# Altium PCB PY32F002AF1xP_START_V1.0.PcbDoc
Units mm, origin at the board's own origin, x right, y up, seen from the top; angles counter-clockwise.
Board outline 53.97 x 29.21 mm, 2 copper layers (Top Layer, Bottom Layer); 29 components, 28 nets, 127 pads, 48 vias.
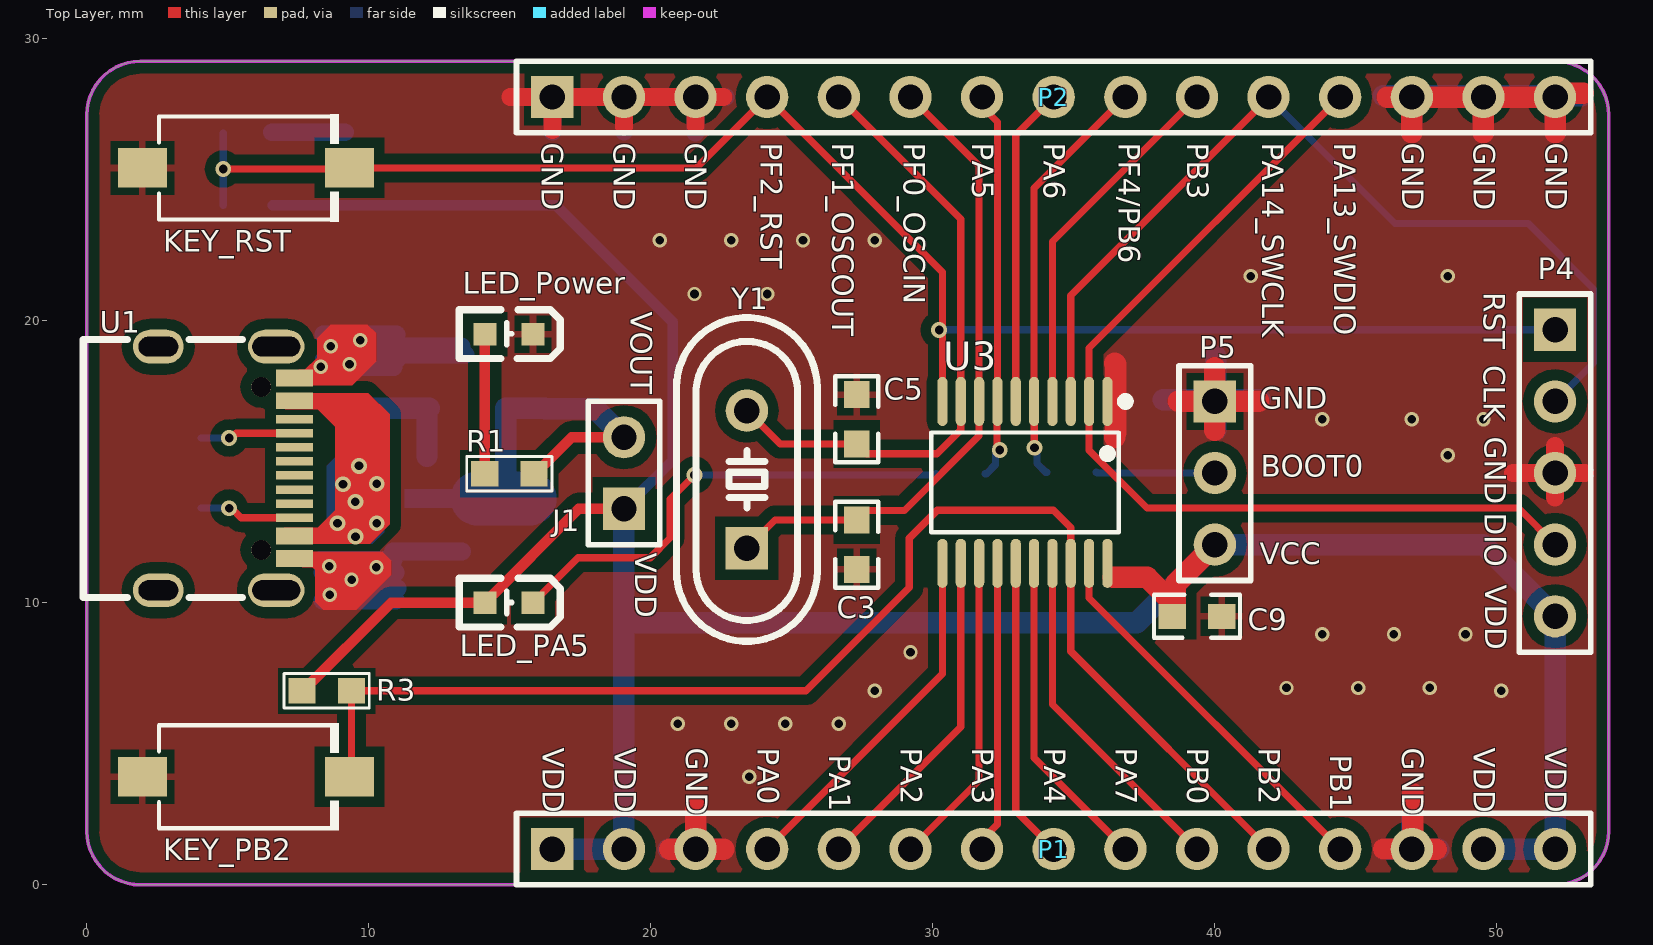
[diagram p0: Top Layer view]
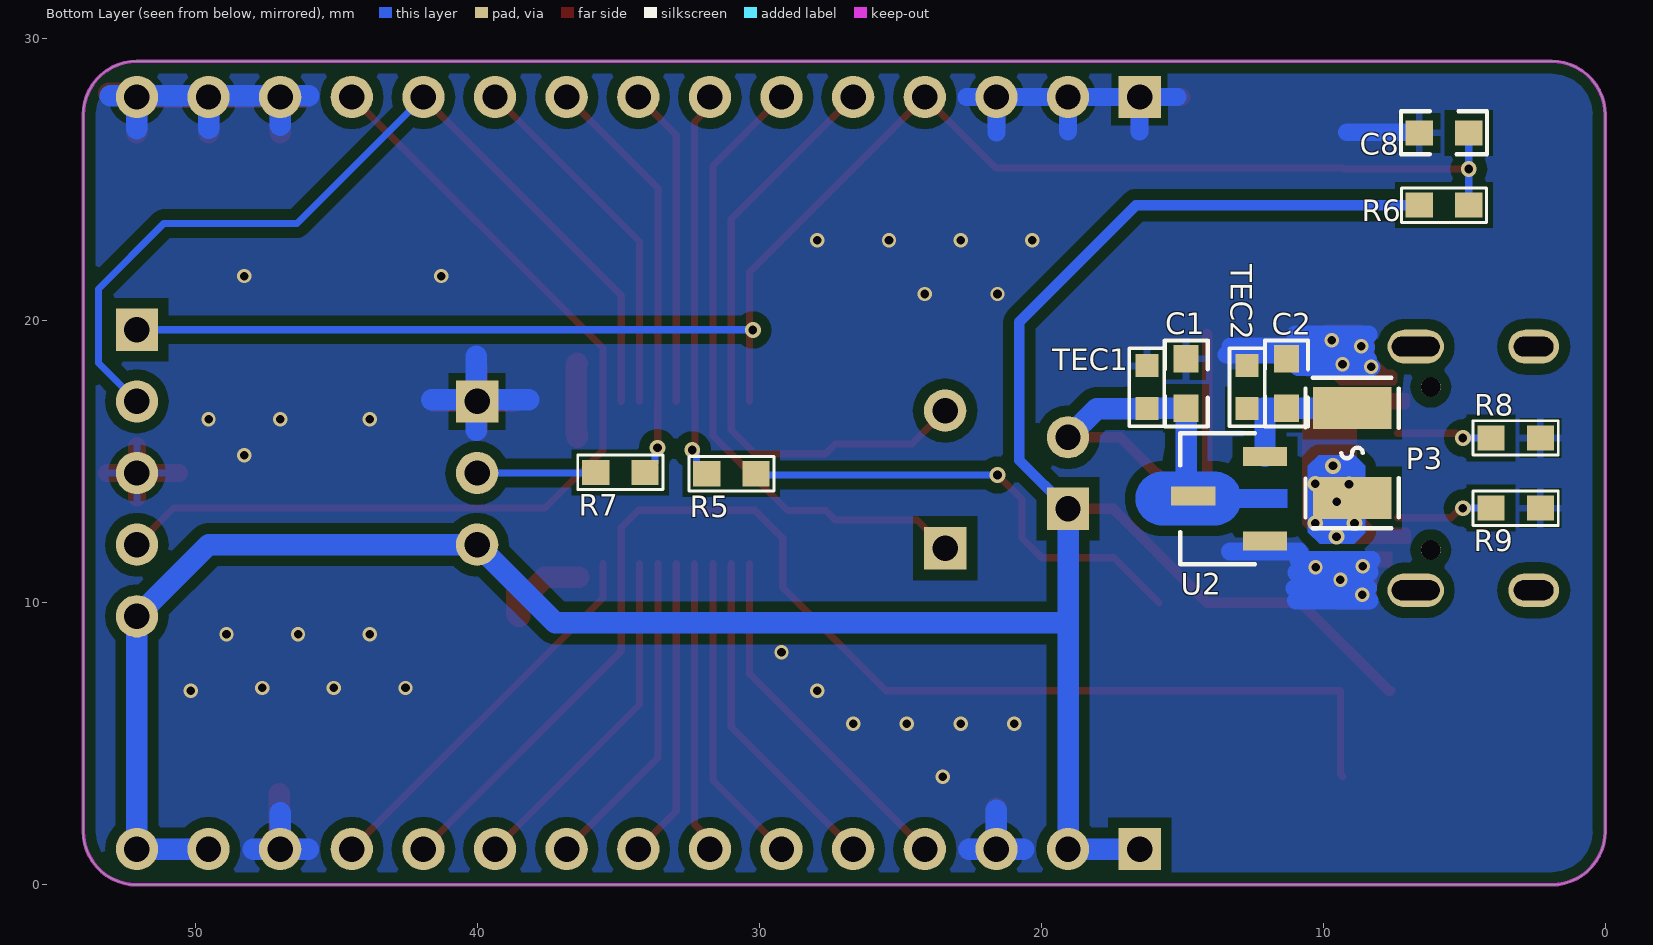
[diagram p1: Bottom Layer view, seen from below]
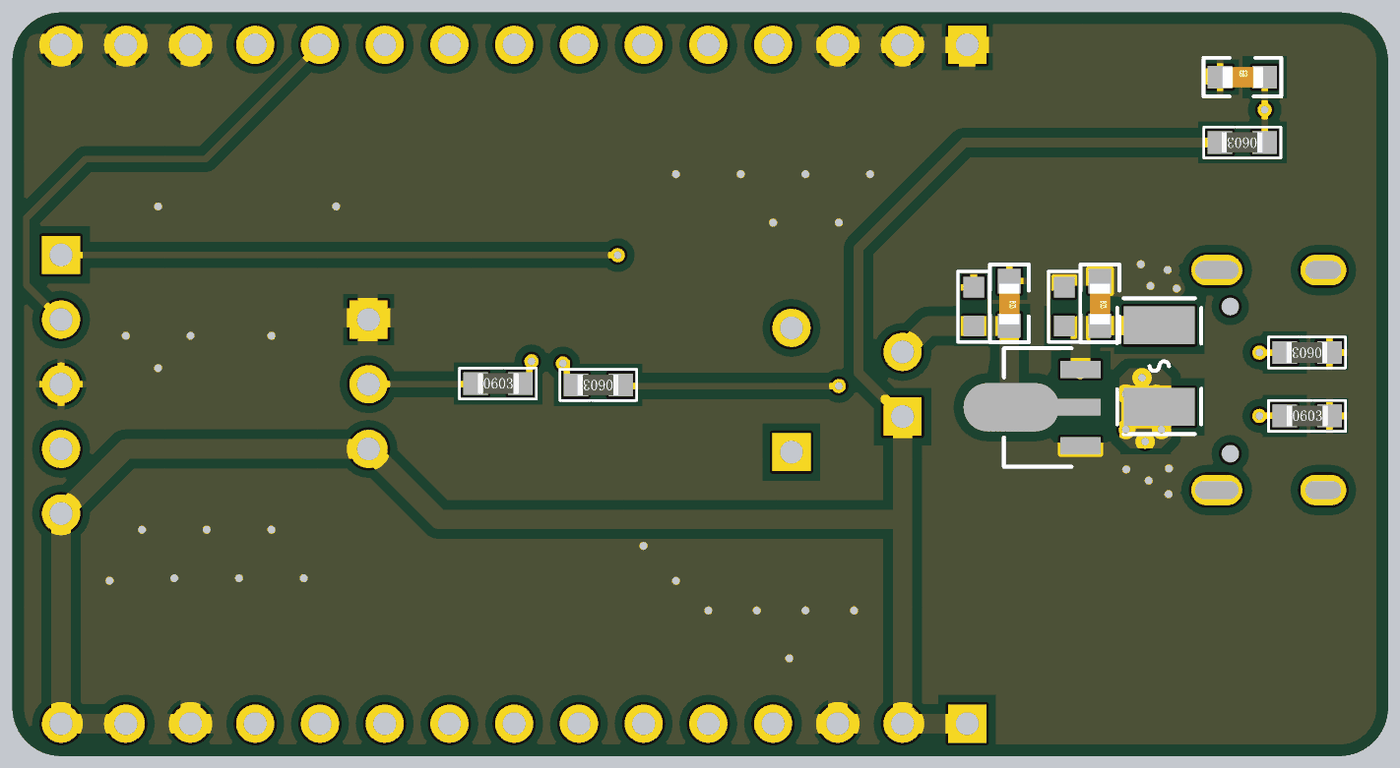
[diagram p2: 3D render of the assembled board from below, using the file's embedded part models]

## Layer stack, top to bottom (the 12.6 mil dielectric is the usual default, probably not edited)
Top Layer: signal copper 0.0356
Dielectric: dielectric 0.32, FR-4, Dk 4.8
Bottom Layer: signal copper 0.0356

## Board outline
0,1.905 0,27.305 cw(c1.905,27.305) 1.905,29.21 52.07,29.21 cw(c52.07,27.305) 53.975,27.305 53.975,1.905 cw(c52.07,1.905) 52.07,0 1.905,0 cw(c1.905,1.905)

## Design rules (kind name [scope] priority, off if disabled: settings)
Clearance [All] p1: gap=0.152
ComponentClearance [All] p1: gap=0 collisioncheckmode=3 verticalgap=0 showdistances=FALSE
HoleToHoleClearance [All] p1: gap=0.076 allowstackedmicrovias=TRUE
MinimumSolderMaskSliver [All] p1: minsoldermaskwidth=0
NetAntennae [All] p1: netantennaetolerance=0.152
PolygonConnect [All] p1: connectstyle=Relief reliefconductorwidth=0.254 reliefentries=4 polygonreliefangle="90 Angle" airgapwidth=0.254
RoutingVias [All] p1: holewidth=0.711 width=1.27 viastyle="Through Hole" minholewidth=0.711 minwidth=1.27 maxholewidth=0.711 maxwidth=1.27
SilkToSilkClearance [All] p1: silktosilkclearance=0
SilkToSolderMaskClearance [IsPad] p1: minsilkscreentomaskgap=0 clearancetoexposedcopper=TRUE
SolderMaskExpansion [All] p1: expansion=0.102
Width [All] p1: maxlimit=0.762 minlimit=0.254 preferedwidth=0.254
22 further rules are at their usual default settings.

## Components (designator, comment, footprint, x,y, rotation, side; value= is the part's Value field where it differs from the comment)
C1 "0.1uF/50V" 0603C 14.859,17.78 r270 bottom
C2 "0.1uF/50V" 0603C 11.303,17.78 r270 bottom
C3 "22pF" 0603C 27.305,12.065 r90 top
C5 "22pF" 0603C 27.305,16.51 r90 top
C8 "0.1uF/50V" 0603C 5.715,26.67 r180 bottom
C9 "0.1uF/50V" 0603C 39.37,9.525 r180 top
J1 "JUMP" HDR1X2 19.05,13.335 r90 top
KEY_PB2 "1TS002B-2600-5001" SW 4.445,3.81 r0 top (schematic designator KEY1)
KEY_RST "1TS002B-2600-5001" SW 4.445,25.4 r0 top (schematic designator RST)
LED_PA5 "GREEN" 0603_LED 14.605,10.033 r180 top (schematic designator LED2)
LED_Power "RED" 0603_LED 14.605,19.558 r180 top (schematic designator LED1)
P1 "Header 15" HDR1X15 16.51,1.27 r0 top
P2 "Header 15" HDR1X15 16.51,27.94 r0 top
P3 "SMD1210P005TF" SDM1210P005TF 9.525,15.24 r90 bottom
P4 "Debug" HDR1X5 52.07,19.685 r270 top
P5 "Header 3" HDR1X3 40.005,17.145 r270 top
R1 "470Ω" 0603R 14.986,14.605 r180 top
R3 "1.5K" 0603R 8.509,6.858 r0 top
R5 "680Ω" 0603R 30.988,14.605 r0 bottom
R6 "10K" 0603R 5.715,24.13 r0 bottom
R7 "10K" 0603R 34.925,14.605 r180 bottom
R8 "5.1k" 0603R 3.175,15.875 r0 bottom
R9 "5.1K" 0603R 3.175,13.335 r180 bottom
TEC1 "10uF" 0603 16.256,17.653 r270 bottom
TEC2 "10uF" 0603 12.7,17.653 r270 bottom
U1 "KH-TYPE-C-16P" USB-C-SMD_KH-TYPE-C-16P 3.81,14.605 r270 top locked
U2 "LM1117-3.3" LM1117-3.3 12.065,12.192 r180 bottom
U3 "PY32F002A" TSSOP20 36.195,17.145 r180 top
Y1 "24M" 25MHZ_2 23.495,15.24 r90 top

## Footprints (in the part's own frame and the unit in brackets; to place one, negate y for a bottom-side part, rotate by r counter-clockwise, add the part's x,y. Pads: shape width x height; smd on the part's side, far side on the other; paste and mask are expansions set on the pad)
25MHZ_2 [mm]
  rect 1.5x1.5 hole 0.9: 1(-3.302,0.087)
  round 1.5 hole 0.9: 2(1.578,0.087)
  silkscreen extent -6.6,-2.41 4.88,2.59
0603 [mil]
  rect 32x32 smd: 1(30,0) 2(-30,0)
  silkscreen extent -54,-25 55,25
0603_LED [mm]
  rect 0.8x0.8 smd: 1(0.483,0.025) 2(-1.219,0.025)
  silkscreen extent -2.18,-0.84 1.4,0.89
0603C [mil]
  rect 38x35 smd: 1(-34.5,0) 2(34.5,0)
  silkscreen extent -60,-30 60,30, body extent -31,-16 32,16, height 12
0603R [mil]
  rect 38x35 smd: 1(-34.5,1) 2(34.5,1)
  silkscreen extent -59,-23 59,25, body extent -31,-15 32,17, height 18
HDR1X2 [mm] "Connector; Header; 2 Position"
  rect 1.5x1.5 hole 0.9: 1(0,0)
  round 1.5 hole 0.9: 2(2.54,0)
  silkscreen extent -1.27,-1.27 3.81,1.27
HDR1X3 [mm] "Connector; Header; 3 Position"
  rect 1.5x1.5 hole 0.9: 1(0,0)
  round 1.5 hole 0.9: 2(2.54,0) 3(5.08,0)
  silkscreen extent -1.27,-1.27 6.35,1.27
HDR1X5 [mm] "Connector; Header; 5 Position"
  rect 1.5x1.5 hole 0.9: 1(0,0)
  round 1.5 hole 0.9: 2(2.54,0) 3(5.08,0) 4(7.62,0) 5(10.16,0)
  silkscreen extent -1.27,-1.27 11.43,1.27
HDR1X15 [mm]
  rect 1.5x1.5 hole 0.9: 1(0,0)
  round 1.5 hole 0.9: 2(2.54,0) 3(5.08,0) 4(7.62,0) 5(10.16,0) 6(12.7,0) 7(15.24,0) 8(17.78,0) 9(20.32,0) 10(22.86,0) 11(25.4,0) 12(27.94,0) 13(30.48,0) 14(33.02,0) 15(35.56,0)
  silkscreen extent -1.27,-1.27 36.83,1.27
LM1117-3.3 [mm]
  rect 1.575x0.672 smd: 1(0,0) 2(-2.55,1.598) 3(0,3)
  Top Layer region: -3.64,2.459 -1.785,2.459 -1.741,2.458 -1.696,2.455 -1.652,2.449 -1.608,2.442 -1.565,2.433 -1.522,2.421 -1.479,2.408 -1.437,2.393 -1.396,2.375 -1.356,2.356 -1.317,2.335 -1.279,2.312 -1.241,2.288 -1.206,2.261 -1.171,2.233 -1.138,2.204 -1.106,2.173 -1.075,2.14 -1.047,2.106 -1.019,2.071 -0.994,2.034 -0.97,1.996 -0.948,1.958 -0.928,1.918 -0.91,1.839 0.788,1.839 0.788,1.179 -0.91,1.179 -0.928,1.099 -0.948,1.06 -0.97,1.021 -0.994,0.983 -1.019,0.947 -1.047,0.911 -1.075,0.877 -1.106,0.845 -1.138,0.814 -1.171,0.784 -1.206,0.756 -1.241,0.73 -1.279,0.705 -1.317,0.682 -1.356,0.661 -1.396,0.642 -1.437,0.625 -1.479,0.609 -1.522,0.596 -1.565,0.585 -1.608,0.575 -1.652,0.568 -1.696,0.563 -1.741,0.56 -1.785,0.559 -3.64,0.559 -3.684,0.56 -3.728,0.563 -3.773,0.568 -3.817,0.575 -3.86,0.585 -3.903,0.596 -3.946,0.609 -3.988,0.625 -4.029,0.642 -4.069,0.661 -4.108,0.682 -4.146,0.705 -4.183,0.73 -4.219,0.756 -4.254,0.784 -4.287,0.814 -4.319,0.845 -4.349,0.877 -4.378,0.911 -4.405,0.947 -4.431,0.983 -4.455,1.021 -4.477,1.06 -4.497,1.099 -4.515,1.14 -4.531,1.181 -4.546,1.224 -4.558,1.266 -4.568,1.31 -4.577,1.353 -4.583,1.398 -4.587,1.442 -4.589,1.486 -4.589,1.531 -4.587,1.575 -4.583,1.62 -4.577,1.664 -4.568,1.708 -4.558,1.751 -4.546,1.794 -4.531,1.836 -4.515,1.877 -4.497,1.918 -4.477,1.958 -4.455,1.996 -4.431,2.034 -4.405,2.071 -4.378,2.106 -4.349,2.14 -4.319,2.173 -4.287,2.204 -4.254,2.233 -4.219,2.261 -4.183,2.288 -4.146,2.312 -4.108,2.335 -4.069,2.356 -4.029,2.375 -3.988,2.393 -3.946,2.408 -3.903,2.421 -3.86,2.433 -3.817,2.442 -3.773,2.449 -3.728,2.455 -3.684,2.458
  silkscreen extent -3.01,-0.83 -0.35,3.83
SDM1210P005TF [mm]
  rect 1.485x2.781 smd: 1(-1.524,-0.549) 2(1.676,-0.549)
  silkscreen extent -2.59,-2.2 2.74,1.1
SW [mm]
  rect 1.74x1.4 smd: 1(-2.476,0.024) 2(4.864,0.024)
  silkscreen extent -1.88,-1.88 4.5,1.93
TSSOP20 [mm]
  oval 0.364x1.742 smd: 1(0,0) 2(0.65,0) 3(1.3,0) 4(1.95,0) 5(2.6,0) 6(3.25,0) 7(3.9,0) 8(4.55,0) 9(5.2,0) 10(5.85,0) 11(5.85,5.742) 12(5.2,5.742) 13(4.55,5.742) 14(3.9,5.742) 15(3.25,5.742) 16(2.6,5.742) 17(1.95,5.742) 18(1.3,5.742) 19(0.65,5.742) 20(0,5.742)
  silkscreen extent -0.78,-0.15 6.25,4.64
USB-C-SMD_KH-TYPE-C-16P [mm] "https://item.szlcsc.com/747093.html"
  oval 1.2x2 hole 0.7 slot 1.7 at 90 deg: 1(-4.484,2.908) 2(4.156,2.908)
  oval 1.2x1.8 hole 0.7 slot 1.4 at 90 deg: 3(-4.484,-1.272) 4(4.156,-1.272)
  rect 0.3x1.3 smd: A1(-3.514,3.558) A4(-2.714,3.558) A5(-1.414,3.558) A6(-0.414,3.558) A7(0.086,3.558) A8(1.086,3.558) A9(2.386,3.558) A12(3.186,3.558) B1(2.886,3.558) B4(2.086,3.558) B5(1.586,3.558) B6(0.586,3.558) B7(-0.914,3.558) B8(-1.914,3.558) B9(-2.414,3.558) B12(-3.214,3.558)
  round 0.7 hole 0.7 unplated: ""(-3.054,2.378) ""(2.726,2.378)
  silkscreen extent -4.74,-3.94 4.41,1.72

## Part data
C1 C3 C5: library part Cap, "Capacitor"
C2 C8 C9: library part CAP, "Capacitor"
LED_PA5 LED_Power: library part PDI-E803_Dup1
P1 P2: "Header, 15-Pin"
P4: library part CON5
P5: "Header, 3-Pin"
R1 R3 R5 R6 R7: library part Res, "Resistor"
R8 R9: library part Res_1, "Resistor"
TEC1 TEC2: library part 贴片钽电容
Y1: library part CRYSTAL, "Crystal"

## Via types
v1: diameter 0.508, hole 0.305, Top Layer to Bottom Layer, tented both sides, 34 vias
v2: diameter 0.559, hole 0.305, Top Layer to Bottom Layer, 14 vias

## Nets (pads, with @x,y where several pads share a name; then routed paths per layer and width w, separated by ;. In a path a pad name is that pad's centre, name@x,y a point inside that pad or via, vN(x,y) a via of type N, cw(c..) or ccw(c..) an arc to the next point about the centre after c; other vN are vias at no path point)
Boot0: P2.9 R7.2 U3.5 | length 14.9
  Top Layer w0.254: v2(33.61,15.505) 33.602,15.512 33.602,17.138 U3.5 33.595,24.705 P2.9
  Bottom Layer w0.254: v2(33.61,15.505) 33.61,15.422 33.693,15.339 33.693,14.948 34.011,14.63 R7.2
GND: C1.1 C2.1 C3.1 C5.2 C8.1 C9.1 KEY_PB2.1 KEY_RST.1 LED_Power.2 P1.3 P1.13 P2.1 P2.2 P2.3 P2.13 P2.14 P2.15 P4.3 P5.1 R8.1 R9.2 TEC1.2 TEC2.2 U1.A1 U1.A12 U1.B1 U1.B12 U2.1 U3.1 | length 105.8
  Top Layer w0.635: 15.018,27.942 22.576,27.942 ; 16.51,26.765 P2.1 ; 19.05,26.884 P2.2 ; 21.59,26.925 P2.3 ; 50.574,14.605 P4.3 ; 52.07,13.742 P4.3 ; 52.07,15.564 P4.3 ; P4.3@52.136,14.671 P4.3 ; 53.134,14.605 P4.3
  Top Layer w0.762: 20.669,1.27 P1.3 ; 21.59,2.711 P1.3 ; 22.586,1.27 P1.3 ; 36.457,15.87 36.457,16.002 36.489,16.033 36.489,18.46 36.457,18.491 ; 38.709,17.145 P5.1 ; 40.005,16.122 P5.1 ; 40.005,18.345 P5.1 ; 41.564,17.145 P5.1 ; 45.989,1.272 P1.13@46.988,1.272 ; 46.121,27.94 P2.13 ; 46.99,26.67 P2.13 ; 47.03,3.239 47.03,1.31 P1.13 47.859,1.27 ; 49.53,26.67 P2.14 ; 52.07,26.67 P2.15 P2.14 ; P2.15@52.35,28.067 53.066,28.067 ; P2.13 P2.14
  Bottom Layer w0.635: C8.1@6.562,26.69 9.163,26.69 ; 8.28,11.527 10.882,11.527 ; v1@8.283,18.37 C2.1@10.884,18.37 ; 8.355,11.084 10.956,11.084 ; 8.365,10.079 10.966,10.079 ; 8.385,19.518 10.987,19.518 ; 8.406,18.626 C2.1@11.007,18.626 ; 8.416,10.52 11.017,10.52 ; v1@8.488,19.067 C2.1@11.089,19.067 ; 10.681,19.098 13.282,19.098 ; 10.824,18.801 13.426,18.801 ; 10.855,11.822 13.304,11.822 ; 15.163,27.94 P2.1 ; 16.51,26.707 P2.1 ; 19.05,26.724 P2.2 ; 21.59,26.674 P2.3 ; 22.65,27.94 P2.3 ; P2.1 P2.2 ; P2.2 P2.3
  Bottom Layer w0.762: 20.629,1.27 P1.3 ; 21.59,2.642 P1.3 ; 22.548,1.27 P1.3 ; 38.176,17.208 P5.1@40.04,17.208 ; 40.04,16.117 P5.1@40.04,17.208 ; 40.04,18.744 P5.1@40.04,17.208 ; 41.617,17.208 P5.1@40.04,17.208 ; 45.972,27.983 53.024,27.983 ; 45.996,1.27 P1.13 ; 46.99,2.559 P1.13 ; 46.99,26.943 P2.13 ; 47.948,1.27 P1.13 ; 49.53,26.824 P2.14 ; 52.07,26.82 P2.15
  other v1: 23.495,3.834 20.955,5.715 22.86,5.715 24.765,5.715 26.67,5.715 27.94,6.883 50.165,6.883 42.545,6.985 45.085,6.985 47.625,6.985 29.21,8.255 43.815,8.89 46.355,8.89 48.895,8.89 8.612,10.284 9.39,10.819 10.271,11.264 8.599,11.296 48.26,15.24 43.815,16.51 46.99,16.51 49.53,16.51 8.292,18.369 9.318,18.467 8.649,19.096 9.698,19.314 21.55,20.955 24.13,20.955 41.275,21.59 48.26,21.59 20.32,22.86 22.86,22.86 25.4,22.86 27.94,22.86
MCU_RST: C8.2 KEY_RST.2 P2.4 P4.1 R6.1 U3.10 | length 58.2
  Top Layer w0.254: v2(4.839,25.387) 9.272,25.387 KEY_RST.2 21.614,25.424 P2.4 30.345,21.725 30.345,19.797 v2(30.226,19.677) 30.345,19.558 U3.10
  Bottom Layer w0.254: R6.1 v2(4.839,25.387) C8.2 ; v2(30.226,19.677) 30.233,19.685 P4.1
MCU_VDD: C9.2 J1.1 LED_PA5.1 P1.1 P1.2 P1.14 P1.15 P4.5 P5.3 R3.1 R6.2 U3.20 | length 104.1
  Top Layer w0.381: R3.1 7.671,6.883 10.795,10.008 LED_PA5.1 17.45,13.335 J1.1
  Top Layer w0.762: 36.394,10.913 37.599,10.913 38.494,10.018 C9.2 38.532,9.525 38.595,9.588 38.595,10.655 P5.3
  Bottom Layer w0.381: R6.2 16.636,24.105 20.776,19.964 20.776,15.061 J1.1
  Bottom Layer w0.762: P1.1 P1.2 19.05,9.291 ; J1.1 19.05,9.291 ; P1.14 P1.15 P4.5 49.53,12.065 P5.3 37.231,9.291 19.05,9.291
NetC1_2: C1.2 J1.2 R1.1 TEC1.1 U2.2 | length 11.7
  Top Layer w0.381: R1.1 15.9,14.58 17.196,15.875 J1.2
  Bottom Layer w0.762: U2.2 14.814,13.79 14.859,13.835 C1.2 14.865,16.897 16.25,16.897 TEC1.1 18.034,16.891 J1.2
NetC2_2: C2.2 P3.2 TEC2.1 U2.3 | length 4.9
  Bottom Layer w0.762: P3.2 8.989,16.903 12.147,16.903 12.065,16.821 U2.3
NetLED1_1: LED_Power.1 R1.2 | length 5
  Top Layer w0.381: R1.2 14.116,14.586 14.116,19.526 LED_Power.1
NetLED2_2: LED_PA5.2 R5.1 | length 17
  Top Layer w0.254: LED_PA5.2 17.415,11.598 19.984,11.598 20.687,12.302 20.687,13.673 v2(21.55,14.536)
  Bottom Layer w0.254: v2(21.55,14.536) 30.068,14.536 R5.1
NetP5_2: P5.2 R7.1 | length 4.2
  Bottom Layer w0.254: R7.1 35.827,14.605 P5.2
NetR8_2: R8.2 U1.A5 | length 3.4
  Top Layer w0.254: v2(5.045,15.848) 5.128,15.848 5.299,16.019 U1.A5
  Bottom Layer w0.254: R8.2 4.053,15.848 v2(5.045,15.848)
NetR9_1: R9.1 U1.B5 | length 3.6
  Top Layer w0.254: v2(5.045,13.36) 5.128,13.36 5.469,13.019 U1.B5
  Bottom Layer w0.254: R9.1 R9.1 5.206,13.361 v2@5.207,13.36
OSCIN: C3.2 P2.6 U3.8 Y1.1 | length 22.9
  Top Layer w0.254: Y1.1 24.411,12.941 C3.2 27.641,13.277 28.998,13.277 31.645,15.925 U3.8 31.645,25.505 P2.6
OSCOUT: C5.1 P2.5 U3.9 Y1.2 | length 22.2
  Top Layer w0.254: Y1.2 24.593,15.634 C5.1 27.652,15.287 30.152,15.287 30.995,16.13 U3.9 30.995,23.615 P2.5
PA0: P1.4 U3.11 | length 12.7
  Top Layer w0.254: P1.4 30.345,7.485 U3.11
PA1: P1.5 U3.12 | length 11.9
  Top Layer w0.254: P1.5 30.995,5.595 U3.12
PA2: P1.6 U3.13 | length 11.1
  Top Layer w0.254: P1.6 31.645,3.705 U3.13
PA3: P1.7 U3.14 | length 10.4
  Top Layer w0.254: P1.7 31.75,1.607 32.295,2.152 U3.14
PA4: P1.8 U3.15 | length 10.7
  Top Layer w0.254: U3.15 32.945,2.615 P1.8
PA5: P2.7 R5.2 U3.7 | length 13.7
  Top Layer w0.254: P2.7 31.75,27.603 32.295,27.058 U3.7 32.274,17.124 v2@32.274,15.527
  Bottom Layer w0.254: R5.2 31.902,14.58 32.22,14.897 v2@32.22,15.473
  other v2: 32.376,15.422
PA6: P2.8 U3.6 | length 11.4
  Top Layer w0.254: U3.6 32.945,26.595 P2.8
PA7: P1.9 U3.16 | length 11.5
  Top Layer w0.254: U3.16 33.595,4.505 P1.9
PB0: P1.10 U3.17 | length 12.3
  Top Layer w0.254: U3.17 34.245,6.395 P1.10
PB1: P1.12 U3.19 | length 13.8
  Top Layer w0.254: U3.19 35.545,10.175 P1.12
PB2: KEY_PB2.2 P1.11 R3.2 U3.18 | length 46.8
  Top Layer w0.254: KEY_PB2.2 9.385,3.911 R3.2 25.504,6.883 29.167,10.546 29.167,12.294 30.157,13.284 34.282,13.284 34.895,12.671 U3.18 34.895,8.285 P1.11
PB3: P2.10 U3.4 | length 12.9
  Top Layer w0.254: U3.4 34.245,22.815 P2.10
SWCLK: P2.11 P4.2 U3.3 | length 32.6
  Top Layer w0.254: U3.3 34.895,20.906 P2.11@41.915,27.926
  Bottom Layer w0.254: P2.11 46.397,23.453 51.118,23.453 53.437,21.134 53.437,18.512 P4.2
SWDIO: P2.12 P4.4 U3.2 | length 34.1
  Top Layer w0.254: P2.12 35.545,19.035 U3.2 35.545,15.411 37.595,13.361 50.774,13.361 P4.4
Type_C: P3.1 U1.A4 U1.A9 U1.B4 U1.B9
  other v2: 9.529,12.35 8.89,12.827 10.287,12.827 9.525,13.589 9.087,14.207 10.287,14.224 9.652,14.859
pads on no net: U1. U1.1 U1.2 U1.3 U1.4 U1.A6 U1.A7 U1.A8 U1.B6 U1.B7 U1.B8

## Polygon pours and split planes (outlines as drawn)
GND on Top Layer "Top-GND" (solid, remove dead copper, pour order 2): -0.016,27.314 -0.016,28.176 0.996,29.188 1.883,29.188 1.905,29.21 53.032,29.21 53.98,28.261 53.98,0.725 53.225,-0.031 1.035,-0.031 -0.006,1.011
GND on Bottom Layer "Top-GND" (solid, remove dead copper, pour order 4): 0,27.305 0,28.114 1.084,29.198 52.876,29.198 53.971,28.103 53.971,1.096 52.865,-0.011 1.147,-0.011 -0.014,1.15

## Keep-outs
Keep-Out Layer:
  the board outline again, w0.127

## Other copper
Top Layer:
  region net Type_C: 10.057,12.089 10.75,12.782 10.75,16.682 9.989,17.443 6.995,17.443 6.927,17.375 6.927,16.977 7.035,16.869 8.185,16.869 8.808,16.246 8.808,13.292 8.184,12.668 7.004,12.668 6.89,12.553 6.89,12.144 6.945,12.089
  region net GND: 7.633,11.271 8.003,11.271 8.102,11.171 8.102,10.047 8.386,9.763 9.56,9.763 10.799,11.002 10.799,11.499 10.479,11.82 7.591,11.82 7.559,11.788 7.559,11.345
  region net GND: 7.738,18.269 8.168,18.699 8.168,19.384 8.654,19.87 9.954,19.87 10.256,19.567 10.256,18.572 9.411,17.727 7.46,17.727 7.368,17.819 7.368,18.119 7.518,18.269
Bottom Layer:
  region net Type_C: 8.89,15.24 8.509,14.859 8.509,12.488 8.908,12.089 10.12,12.089 10.541,12.51 10.541,14.859 10.16,15.24

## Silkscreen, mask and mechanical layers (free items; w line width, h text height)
Top Overlay:
  text "GND" at 16.139,26.319 h0.76 r270
  text "GND" at 18.681,26.319 h0.76 r270
  text "GND" at 21.224,26.319 h0.76 r270
  text "PF2_RST" at 23.893,26.319 h0.76 r270
  text "PF1_OSCOUT" at 26.435,26.319 h0.76 r270
  text "PF0_OSCIN" at 28.978,26.319 h0.76 r270
  text "PA5" at 31.393,26.319 h0.76 r270
  text "PA6" at 33.936,26.319 h0.76 r270
  text "PF4/PB6" at 36.605,26.319 h0.76 r270
  text "PB3" at 39.02,26.319 h0.76 r270
  text "PA14_SWCLK" at 41.69,26.319 h0.76 r270
  text "PA13_SWDIO" at 44.232,26.319 h0.76 r270
  text "GND" at 46.647,26.319 h0.76 r270
  text "GND" at 49.19,26.319 h0.76 r270
  text "GND" at 51.732,26.319 h0.76 r270
  text "RST" at 49.543,21.015 h0.76 r270
  text "VOUT" at 19.284,20.32 h0.76 r270
  text "CLK" at 49.543,18.424 h0.76 r270
  text "GND" at 41.593,16.884 h0.76
  text "GND" at 49.569,15.884 h0.76 r270
  text "BOOT0" at 41.635,14.477 h0.76
  text "DIO" at 49.569,13.192 h0.76 r270
  text "VDD" at 19.442,11.78 h0.76 r270
  text "VCC" at 41.602,11.368 h0.76
  text "VDD" at 49.594,10.652 h0.76 r270
  text "VDD" at 16.176,4.867 h0.76 r270
  text "VDD" at 18.715,4.867 h0.76 r270
  text "GND" at 21.254,4.867 h0.76 r270
  text "PA0" at 23.793,4.867 h0.76 r270
  text "PA2" at 28.87,4.867 h0.76 r270
  text "PA3" at 31.409,4.867 h0.76 r270
  text "PA4" at 33.948,4.867 h0.76 r270
  text "PA7" at 36.487,4.867 h0.76 r270
  text "PB0" at 39.026,4.867 h0.76 r270
  text "PB2" at 41.565,4.867 h0.76 r270
  text "GND" at 46.643,4.867 h0.76 r270
  text "VDD" at 49.181,4.867 h0.76 r270
  text "VDD" at 51.72,4.867 h0.76 r270
  text "PA1" at 26.331,4.614 h0.76 r270
  text "PB1" at 44.104,4.614 h0.76 r270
